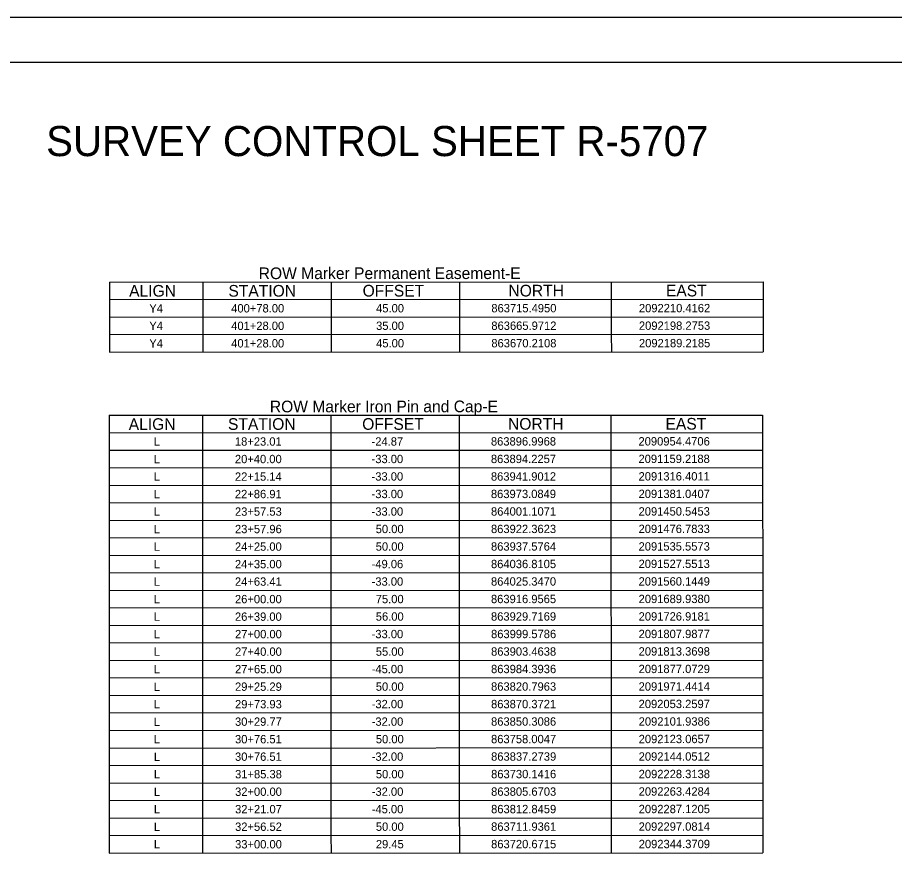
# Model space of a CAD drawing. Extents: x 2093228 to 2098328, y 861854 to 865154.
# Drawn here: x 2095387 to 2096858, y 863710 to 865154 of the extents above; entities that cross this region are included whole.
import ezdxf

# ---------------------------------------------------------------- set-up
doc = ezdxf.new("R2010")
doc.units = 0
for name, color, linetype in [('CTL Sheet Border CELL', 7, 'Continuous'), ('CTL Sheet Notes CELL', 7, 'Continuous'), ('CTL Sheet Table Cell', 7, 'Continuous'), ('CTL Sheet Text', 7, 'Continuous'), ('Sheet Plan CELL', 7, 'Continuous'), ('Sheet Plot Border Inside CELL', 7, 'Continuous')]:
    doc.layers.add(name, color=color, linetype=linetype)

msp = doc.modelspace()

# ---------------------------------------------------------------- linework, layer by layer
at = {"layer": 'CTL Sheet Table Cell'}
for p, q in [((2095541, 864710.4), (2096637.2, 864710.9)), ((2095541, 864710.4), (2095541, 864681.1)), ((2095697.6, 864710.5), (2095697.6, 864681.1)), ((2095912.9, 864710.6), (2095912.9, 864681.2)), ((2096128.2, 864710.7), (2096128.2, 864681.3)), ((2096382.7, 864710.8), (2096382.7, 864681.5)), ((2096637.2, 864710.9), (2096637.2, 864681.6)), ((2095541, 864681.1), (2096637.2, 864681.6)), ((2095541, 864681.1), (2095541, 864651.7)), ((2095697.6, 864681.1), (2095697.6, 864651.8)), ((2095912.9, 864681.2), (2095912.9, 864651.9)), ((2096128.2, 864681.3), (2096128.3, 864652)), ((2096382.7, 864681.5), (2096382.7, 864652.1)), ((2096637.2, 864681.6), (2096637.2, 864652.2)), ((2095541, 864651.7), (2096637.2, 864652.2)), ((2095541, 864651.7), (2095541, 864622.3)), ((2095697.6, 864651.8), (2095697.6, 864622.4)), ((2095912.9, 864651.9), (2095913, 864622.5)), ((2096128.3, 864652), (2096128.3, 864622.6)), ((2096382.7, 864652.1), (2096382.7, 864622.7)), ((2096637.2, 864652.2), (2096637.2, 864622.9)), ((2095541, 864622.3), (2096637.2, 864622.9)), ((2095541, 864622.3), (2095541.1, 864593)), ((2095697.6, 864622.4), (2095697.6, 864593)), ((2095913, 864622.5), (2095913, 864593.1)), ((2096128.3, 864622.6), (2096128.3, 864593.3)), ((2096382.7, 864622.7), (2096382.8, 864593.4)), ((2096637.2, 864622.9), (2096637.2, 864593.5)), ((2095541.1, 864593), (2096637.2, 864593.5)), ((2095540.3, 864487), (2096636.5, 864487.5)), ((2095540.3, 864487), (2095540.3, 864457.6)), ((2095696.9, 864487.1), (2095696.9, 864457.7)), ((2095912.2, 864487.2), (2095912.2, 864457.8)), ((2096127.5, 864487.3), (2096127.5, 864457.9)), ((2096382, 864487.4), (2096382, 864458)), ((2096636.5, 864487.5), (2096636.5, 864458.2)), ((2095540.3, 864457.6), (2096636.5, 864458.2)), ((2096636.5, 864458.2), (2096636.5, 864428.8)), ((2095540.3, 864457.6), (2095540.3, 864428.3)), ((2095696.9, 864457.7), (2095696.9, 864428.3)), ((2095912.2, 864457.8), (2095912.2, 864428.5)), ((2096127.5, 864457.9), (2096127.6, 864428.6)), ((2096382, 864458), (2096382, 864428.7)), ((2095540.3, 864428.3), (2096636.5, 864428.8)), ((2096636.5, 864428.8), (2096636.5, 864399.4)), ((2095540.3, 864428.3), (2095540.3, 864398.9)), ((2095696.9, 864428.3), (2095696.9, 864399)), ((2095912.2, 864428.5), (2095912.2, 864399.1)), ((2096127.6, 864428.6), (2096127.6, 864399.2)), ((2096382, 864428.7), (2096382, 864399.3)), ((2095540.3, 864398.9), (2096636.5, 864399.4)), ((2096382, 864399.3), (2096382, 864370)), ((2096636.5, 864399.4), (2096636.5, 864370.1)), ((2095540.3, 864398.9), (2095540.3, 864369.6)), ((2095696.9, 864399), (2095696.9, 864369.6)), ((2095912.2, 864399.1), (2095912.3, 864369.7)), ((2096127.6, 864399.2), (2096127.6, 864369.8)), ((2095540.3, 864369.6), (2096636.5, 864370.1)), ((2096382, 864370), (2096382.1, 864340.6)), ((2096636.5, 864370.1), (2096636.5, 864340.7)), ((2095540.3, 864369.6), (2095540.4, 864340.2)), ((2095696.9, 864369.6), (2095697, 864340.3)), ((2095912.3, 864369.7), (2095912.3, 864340.4)), ((2096127.6, 864369.8), (2096127.6, 864340.5)), ((2095540.4, 864340.2), (2096636.5, 864340.7)), ((2096382.1, 864340.6), (2096382.1, 864311.2)), ((2096636.5, 864340.7), (2096636.5, 864311.4)), ((2095540.4, 864340.2), (2095540.4, 864310.8)), ((2095697, 864340.3), (2095697, 864310.9)), ((2095912.3, 864340.4), (2095912.3, 864311)), ((2096127.6, 864340.5), (2096127.6, 864311.1)), ((2095540.4, 864310.8), (2096636.5, 864311.4)), ((2096127.6, 864311.1), (2096127.6, 864281.7)), ((2096382.1, 864311.2), (2096382.1, 864281.9)), ((2096636.5, 864311.4), (2096636.6, 864282)), ((2095540.4, 864310.8), (2095540.4, 864281.5)), ((2095697, 864310.9), (2095697, 864281.5)), ((2095912.3, 864311), (2095912.3, 864281.6)), ((2095540.4, 864281.5), (2096636.6, 864282)), ((2095912.3, 864281.6), (2095912.3, 864252.3)), ((2096127.6, 864281.7), (2096127.6, 864252.4)), ((2096382.1, 864281.9), (2096382.1, 864252.5)), ((2096636.6, 864282), (2096636.6, 864252.6)), ((2095540.4, 864281.5), (2095540.4, 864252.1)), ((2095697, 864281.5), (2095697, 864252.2)), ((2095540.4, 864252.1), (2096636.6, 864252.6)), ((2095912.3, 864252.3), (2095912.3, 864222.9)), ((2096127.6, 864252.4), (2096127.6, 864223)), ((2096382.1, 864252.5), (2096382.1, 864223.1)), ((2096636.6, 864252.6), (2096636.6, 864223.3)), ((2095540.4, 864252.1), (2095540.4, 864222.7)), ((2095697, 864252.2), (2095697, 864222.8)), ((2095540.4, 864222.7), (2096636.6, 864223.3)), ((2095697, 864222.8), (2095697, 864193.5)), ((2095912.3, 864222.9), (2095912.3, 864193.6)), ((2096127.6, 864223), (2096127.7, 864193.7)), ((2096382.1, 864223.1), (2096382.1, 864193.8)), ((2096636.6, 864223.3), (2096636.6, 864193.9)), ((2095540.4, 864222.7), (2095540.4, 864193.4)), ((2095540.4, 864193.4), (2096636.6, 864193.9)), ((2095697, 864193.5), (2095697, 864164.1)), ((2095912.3, 864193.6), (2095912.4, 864164.2)), ((2096127.7, 864193.7), (2096127.7, 864164.3)), ((2096382.1, 864193.8), (2096382.1, 864164.4)), ((2096636.6, 864193.9), (2096636.6, 864164.5)), ((2095540.4, 864193.4), (2095540.4, 864164)), ((2095540.4, 864164), (2096636.6, 864164.5)), ((2095540.4, 864164), (2095540.5, 864134.7)), ((2095697, 864164.1), (2095697.1, 864134.7)), ((2095912.4, 864164.2), (2095912.4, 864134.8)), ((2096127.7, 864164.3), (2096127.7, 864134.9)), ((2096382.1, 864164.4), (2096382.2, 864135.1)), ((2096636.6, 864164.5), (2096636.6, 864135.2)), ((2095540.5, 864134.7), (2096636.6, 864135.2)), ((2095540.5, 864134.7), (2095540.5, 864105.3)), ((2095697.1, 864134.7), (2095697.1, 864105.4)), ((2095912.4, 864134.8), (2095912.4, 864105.5)), ((2096127.7, 864134.9), (2096127.7, 864105.6)), ((2096382.2, 864135.1), (2096382.2, 864105.7)), ((2096636.6, 864135.2), (2096636.6, 864105.8)), ((2095540.5, 864105.3), (2096636.6, 864105.8)), ((2095540.5, 864105.3), (2095540.5, 864075.9)), ((2095697.1, 864105.4), (2095697.1, 864076)), ((2095912.4, 864105.5), (2095912.4, 864076.1)), ((2096127.7, 864105.6), (2096127.7, 864076.2)), ((2096382.2, 864105.7), (2096382.2, 864076.3)), ((2096636.6, 864105.8), (2096636.7, 864076.5)), ((2095540.5, 864075.9), (2096636.7, 864076.5)), ((2095540.5, 864075.9), (2095540.5, 864046.6)), ((2095697.1, 864076), (2095697.1, 864046.6)), ((2095912.4, 864076.1), (2095912.4, 864046.8)), ((2096127.7, 864076.2), (2096127.7, 864046.9)), ((2096382.2, 864076.3), (2096382.2, 864047)), ((2096636.7, 864076.5), (2096636.7, 864047.1)), ((2095540.5, 864046.6), (2096636.7, 864047.1)), ((2095540.5, 864046.6), (2095540.5, 864017.2)), ((2095697.1, 864046.6), (2095697.1, 864017.3)), ((2095912.4, 864046.8), (2095912.4, 864017.4)), ((2096127.7, 864046.9), (2096127.7, 864017.5)), ((2096382.2, 864047), (2096382.2, 864017.6)), ((2096636.7, 864047.1), (2096636.7, 864017.7)), ((2095540.5, 864017.2), (2096636.7, 864017.7)), ((2095540.5, 864017.2), (2095540.5, 863987.9)), ((2095697.1, 864017.3), (2095697.1, 863987.9)), ((2095912.4, 864017.4), (2095912.4, 863988)), ((2096127.7, 864017.5), (2096127.8, 863988.1)), ((2096382.2, 864017.6), (2096382.2, 863988.3)), ((2096636.7, 864017.7), (2096636.7, 863988.4)), ((2095540.5, 863987.9), (2096636.7, 863988.4)), ((2095540.5, 863987.9), (2095540.5, 863958.5)), ((2095697.1, 863987.9), (2095697.1, 863958.6)), ((2095912.4, 863988), (2095912.5, 863958.7)), ((2096127.8, 863988.1), (2096127.8, 863958.8)), ((2096382.2, 863988.3), (2096382.2, 863958.9)), ((2096636.7, 863988.4), (2096636.7, 863959)), ((2095540.5, 863958.5), (2096636.7, 863959)), ((2095540.5, 863958.5), (2095540.6, 863929.1)), ((2095697.1, 863958.6), (2095697.2, 863929.2)), ((2095912.5, 863958.7), (2095912.5, 863929.3)), ((2096127.8, 863958.8), (2096127.8, 863929.4)), ((2096382.2, 863958.9), (2096382.3, 863929.5)), ((2096636.7, 863959), (2096636.7, 863929.7)), ((2095540.6, 863929.1), (2096636.7, 863929.7)), ((2095540.6, 863929.1), (2095540.6, 863899.8)), ((2095697.2, 863929.2), (2095697.2, 863899.8)), ((2095912.5, 863929.3), (2095912.5, 863899.9)), ((2096127.8, 863929.4), (2096127.8, 863900)), ((2096382.3, 863929.5), (2096382.3, 863900.2)), ((2096636.7, 863929.7), (2096636.7, 863900.3)), ((2095540.6, 863899.8), (2096636.7, 863900.3)), ((2095540.6, 863899.8), (2095540.6, 863870.4)), ((2095697.2, 863899.8), (2095697.2, 863870.5)), ((2095912.5, 863899.9), (2095912.5, 863870.6)), ((2096127.8, 863900), (2096127.8, 863870.7)), ((2096382.3, 863900.2), (2096382.3, 863870.8)), ((2096636.7, 863900.3), (2096636.8, 863870.9)), ((2095540.6, 863870.4), (2096636.8, 863870.9)), ((2095540.6, 863870.4), (2095540.6, 863841)), ((2095697.2, 863870.5), (2095697.2, 863841.1)), ((2095912.5, 863870.6), (2095912.5, 863841.2)), ((2096127.8, 863870.7), (2096127.8, 863841.3)), ((2096382.3, 863870.8), (2096382.3, 863841.4)), ((2096636.8, 863870.9), (2096636.8, 863841.6)), ((2095540.6, 863841), (2096636.8, 863841.6)), ((2095540.6, 863841), (2095540.6, 863811.7)), ((2095697.2, 863841.1), (2095697.2, 863811.8)), ((2095912.5, 863841.2), (2095912.5, 863811.9)), ((2096127.8, 863841.3), (2096127.8, 863812)), ((2096382.3, 863841.4), (2096382.3, 863812.1)), ((2096636.8, 863841.6), (2096636.8, 863812.2)), ((2095540.6, 863811.7), (2096636.8, 863812.2)), ((2095540.6, 863811.7), (2095540.6, 863782.3)), ((2095697.2, 863811.8), (2095697.2, 863782.4)), ((2095912.5, 863811.9), (2095912.5, 863782.5)), ((2096127.8, 863812), (2096127.9, 863782.6)), ((2096382.3, 863812.1), (2096382.3, 863782.7)), ((2096636.8, 863812.2), (2096636.8, 863782.8)), ((2095540.6, 863782.3), (2096636.8, 863782.8)), ((2095540.6, 863782.3), (2095540.6, 863753)), ((2095697.2, 863782.4), (2095697.2, 863753)), ((2095912.5, 863782.5), (2095912.6, 863753.1)), ((2096127.9, 863782.6), (2096127.9, 863753.2)), ((2096382.3, 863782.7), (2096382.3, 863753.4)), ((2096636.8, 863782.8), (2096636.8, 863753.5)), ((2095540.6, 863753), (2096636.8, 863753.5))]:
    msp.add_line(p, q, dxfattribs=at)
at = {"layer": 'Sheet Plan CELL'}
msp.add_lwpolyline([(2093753.4, 865079.1), (2098253.4, 865079.1), (2098253.4, 861929.1), (2093753.4, 861929.1)], close=True, dxfattribs=at)
at = {"layer": 'Sheet Plot Border Inside CELL'}
msp.add_lwpolyline([(2098328.4, 865154.1), (2093228.4, 865154.1), (2093228.4, 861854.1), (2098328.4, 861854.1)], close=True, dxfattribs=at)

# ---------------------------------------------------------------- texts
at = {"layer": 'CTL Sheet Border CELL'}
msp.add_text('SURVEY CONTROL SHEET R-5707 ', height=50.504, dxfattribs=at).set_placement((2095434.8, 864921.7))
at = {"layer": 'CTL Sheet Notes CELL'}
for s, height, p in [('ROW Marker Permanent Easement-E', 19.574, (2095791.3, 864715.4)), ('ALIGN', 19.57, (2095574, 864686)), ('STATION', 19.57, (2095740.5, 864686)), ('OFFSET', 19.57, (2095965.6, 864686.2)), ('NORTH', 19.57, (2096210.2, 864686.3)), ('EAST', 19.57, (2096474.3, 864686.4)), ('ROW Marker Iron Pin and Cap-E', 19.574, (2095810, 864492)), ('ALIGN', 19.57, (2095573.3, 864462.5)), ('STATION', 19.57, (2095739.8, 864462.6)), ('OFFSET', 19.57, (2095964.9, 864462.7)), ('NORTH', 19.57, (2096209.5, 864462.9)), ('EAST', 19.57, (2096473.6, 864463))]:
    msp.add_text(s, height=height, rotation=0.0276, dxfattribs=at).set_placement(p)
at = {"layer": 'CTL Sheet Text'}
for s, height, p in [('Y4', 13.98, (2095607.8, 864659.4)), ('400+78.00', 13.98, (2095745.2, 864659.5)), ('45.00', 13.98, (2095988.2, 864659.6)), ('863715.4950', 13.982, (2096181.5, 864659.7)), ('2092210.4162', 13.982, (2096429, 864659.8)), ('Y4', 13.98, (2095607.8, 864630.1)), ('401+28.00', 13.98, (2095745.2, 864630.1)), ('35.00', 13.98, (2095988.2, 864630.2)), ('863665.9712', 13.982, (2096181.5, 864630.3)), ('2092198.2753', 13.982, (2096429, 864630.4)), ('Y4', 13.98, (2095607.8, 864600.7)), ('401+28.00', 13.98, (2095745.2, 864600.8)), ('45.00', 13.98, (2095988.3, 864600.9)), ('863670.2108', 13.982, (2096181.5, 864601)), ('2092189.2185', 13.982, (2096429.1, 864601.1)), ('L', 14, (2095615.2, 864436)), ('18+23.01', 13.98, (2095751.4, 864436.1)), ('-24.87', 13.98, (2095980.6, 864436.2)), ('863896.9968', 13.982, (2096180.8, 864436.3)), ('2090954.4706', 13.982, (2096428.3, 864436.4)), ('L', 14, (2095615.2, 864406.6)), ('20+40.00', 13.98, (2095751.4, 864406.7)), ('-33.00', 13.98, (2095980.6, 864406.8)), ('863894.2257', 13.982, (2096180.8, 864406.9)), ('2091159.2188', 13.982, (2096428.3, 864407)), ('L', 14, (2095615.2, 864377.3)), ('22+15.14', 13.98, (2095751.4, 864377.3)), ('-33.00', 13.98, (2095980.6, 864377.5)), ('863941.9012', 13.982, (2096180.8, 864377.5)), ('2091316.4011', 13.982, (2096428.4, 864377.7)), ('L', 14, (2095615.2, 864347.9)), ('22+86.91', 13.98, (2095751.4, 864348)), ('-33.00', 13.98, (2095980.6, 864348.1)), ('863973.0849', 13.982, (2096180.8, 864348.2)), ('2091381.0407', 13.982, (2096428.4, 864348.3)), ('L', 14, (2095615.3, 864318.6)), ('23+57.53', 13.98, (2095751.5, 864318.6)), ('-33.00', 13.98, (2095980.6, 864318.7)), ('864001.1071', 13.982, (2096180.9, 864318.8)), ('2091450.5453', 13.982, (2096428.4, 864318.9)), ('L', 14, (2095615.3, 864289.2)), ('23+57.96', 13.98, (2095751.5, 864289.3)), ('50.00', 13.98, (2095987.6, 864289.4)), ('863922.3623', 13.982, (2096180.9, 864289.5)), ('2091476.7833', 13.982, (2096428.4, 864289.6)), ('L', 14, (2095615.3, 864259.8)), ('24+25.00', 13.98, (2095751.5, 864259.9)), ('50.00', 13.98, (2095987.6, 864260)), ('863937.5764', 13.982, (2096180.9, 864260.1)), ('2091535.5573', 13.982, (2096428.4, 864260.2)), ('L', 14, (2095615.3, 864230.5)), ('24+35.00', 13.98, (2095751.5, 864230.5)), ('-49.06', 13.98, (2095980.7, 864230.6)), ('864036.8105', 13.982, (2096180.9, 864230.7)), ('2091527.5513', 13.982, (2096428.4, 864230.9)), ('L', 14, (2095615.3, 864201.1)), ('24+63.41', 13.98, (2095751.5, 864201.2)), ('-33.00', 13.98, (2095980.7, 864201.3)), ('864025.3470', 13.982, (2096180.9, 864201.4)), ('2091560.1449', 13.982, (2096428.4, 864201.5)), ('L', 14, (2095615.3, 864171.7)), ('26+00.00', 13.98, (2095751.5, 864171.8)), ('75.00', 13.98, (2095987.6, 864171.9)), ('863916.9565', 13.982, (2096180.9, 864172)), ('2091689.9380', 13.982, (2096428.5, 864172.1)), ('L', 14, (2095615.3, 864142.4)), ('26+39.00', 13.98, (2095751.5, 864142.4)), ('56.00', 13.98, (2095987.7, 864142.6)), ('863929.7169', 13.982, (2096180.9, 864142.7)), ('2091726.9181', 13.982, (2096428.5, 864142.8)), ('L', 14, (2095615.4, 864113)), ('27+00.00', 13.98, (2095751.6, 864113.1)), ('-33.00', 13.98, (2095980.7, 864113.2)), ('863999.5786', 13.982, (2096181, 864113.3)), ('2091807.9877', 13.982, (2096428.5, 864113.4)), ('L', 14, (2095615.4, 864083.7)), ('27+40.00', 13.98, (2095751.6, 864083.7)), ('55.00', 13.98, (2095987.7, 864083.8)), ('863903.4638', 13.982, (2096181, 864083.9)), ('2091813.3698', 13.982, (2096428.5, 864084.1)), ('L', 14, (2095615.4, 864054.3)), ('27+65.00', 13.98, (2095751.6, 864054.4)), ('-45.00', 13.98, (2095980.8, 864054.5)), ('863984.3936', 13.982, (2096181, 864054.6)), ('2091877.0729', 13.982, (2096428.5, 864054.7)), ('L', 14, (2095615.4, 864024.9)), ('29+25.29', 13.98, (2095751.6, 864025)), ('50.00', 13.98, (2095987.7, 864025.1)), ('863820.7963', 13.982, (2096181, 864025.2)), ('2091971.4414', 13.982, (2096428.5, 864025.3)), ('L', 14, (2095615.4, 863995.6)), ('29+73.93', 13.98, (2095751.6, 863995.6)), ('-32.00', 13.98, (2095980.8, 863995.8)), ('863870.3721', 13.982, (2096181, 863995.8)), ('2092053.2597', 13.982, (2096428.5, 863996)), ('L', 14, (2095615.4, 863966.2)), ('30+29.77', 13.98, (2095751.6, 863966.3)), ('-32.00', 13.98, (2095980.8, 863966.4)), ('863850.3086', 13.982, (2096181, 863966.5)), ('2092101.9386', 13.982, (2096428.6, 863966.6)), ('L', 14, (2095615.4, 863936.9)), ('30+76.51', 13.98, (2095751.6, 863936.9)), ('50.00', 13.98, (2095987.8, 863937)), ('863758.0047', 13.982, (2096181, 863937.1)), ('2092123.0657', 13.982, (2096428.6, 863937.2)), ('L', 14, (2095615.5, 863907.5)), ('30+76.51', 13.98, (2095751.6, 863907.6)), ('-32.00', 13.98, (2095980.8, 863907.7)), ('863837.2739', 13.982, (2096181.1, 863907.8)), ('2092144.0512', 13.982, (2096428.6, 863907.9)), ('L', 14, (2095615.5, 863878.1)), ('31+85.38', 13.98, (2095751.7, 863878.2)), ('50.00', 13.98, (2095987.8, 863878.3)), ('863730.1416', 13.982, (2096181.1, 863878.4)), ('2092228.3138', 13.982, (2096428.6, 863878.5)), ('L', 14, (2095615.5, 863848.8)), ('32+00.00', 13.98, (2095751.7, 863848.8)), ('-32.00', 13.98, (2095980.9, 863848.9)), ('863805.6703', 13.982, (2096181.1, 863849)), ('2092263.4284', 13.982, (2096428.6, 863849.2)), ('L', 14, (2095615.5, 863819.4)), ('32+21.07', 13.98, (2095751.7, 863819.5)), ('-45.00', 13.98, (2095980.9, 863819.6)), ('863812.8459', 13.982, (2096181.1, 863819.7)), ('2092287.1205', 13.982, (2096428.6, 863819.8)), ('L', 14, (2095615.5, 863790)), ('32+56.52', 13.98, (2095751.7, 863790.1)), ('50.00', 13.98, (2095987.8, 863790.2)), ('863711.9361', 13.982, (2096181.1, 863790.3)), ('2092297.0814', 13.982, (2096428.6, 863790.4)), ('L', 14, (2095615.5, 863760.7)), ('33+00.00', 13.98, (2095751.7, 863760.7)), ('29.45', 13.98, (2095987.8, 863760.9)), ('863720.6715', 13.982, (2096181.1, 863761)), ('2092344.3709', 13.982, (2096428.7, 863761.1))]:
    msp.add_text(s, height=height, rotation=0.0276, dxfattribs=at).set_placement(p)

doc.saveas('drawing.dxf')
